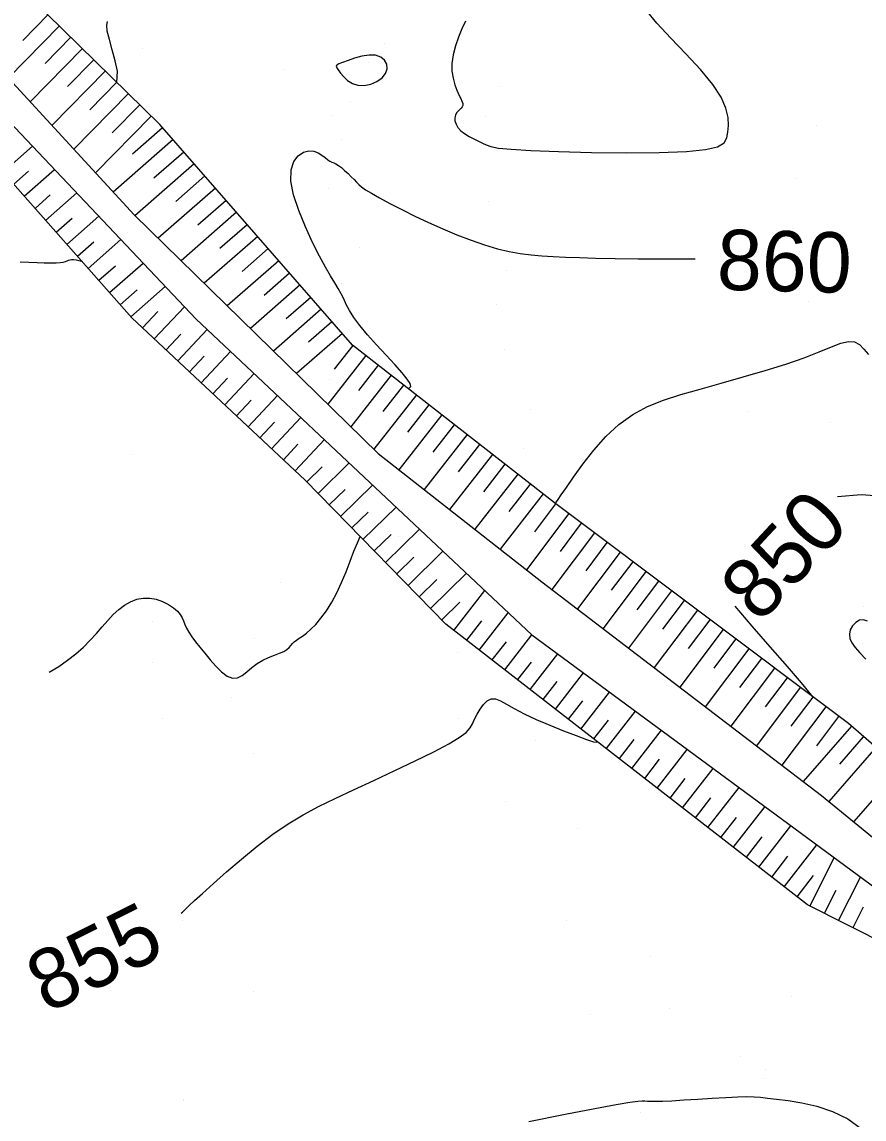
# Model space of a CAD drawing. Extents: x 400243 to 403697, y 4403637 to 4408083.
# Drawn here: x 402920.2 to 403024.9, y 4406214.4 to 4406350.8 of the extents above; entities that cross this region are included whole.
import ezdxf

# ---------------------------------------------------------------- set-up
doc = ezdxf.new("R2010")
doc.units = 0
doc.layers.add('HH_IC', color=7, linetype='Continuous')

msp = doc.modelspace()

# ---------------------------------------------------------------- linework, layer by layer
at = {"layer": 'HH_IC'}
for p, q in [((402937.32, 4406338.07), (402905.56, 4406369.26)), ((402902.34, 4406361.38), (402934.09, 4406326.86)), ((402933.83, 4406314.03), (402899.67, 4406352.63)), ((402920.25, 4406348.54), (402923.4, 4406351.74)), ((402924.82, 4406350.34), (402918.46, 4406343.86)), ((402923.03, 4406345.66), (402926.25, 4406348.94)), ((402927.68, 4406347.54), (402921.17, 4406340.91)), ((402965.24, 4406348.17), (402965.24, 4406348.17)), ((402935.15, 4406347.47), (402935.15, 4406347.47)), ((402925.82, 4406342.79), (402929.11, 4406346.14)), ((402952.66, 4406344.92), (402952.66, 4406344.92)), ((402963.19, 4406345.75), (402963.19, 4406345.75)), ((402930.53, 4406344.74), (402923.88, 4406337.96)), ((402914.74, 4406342.46), (402941.82, 4406313.88)), ((402928.6, 4406339.91), (402931.96, 4406343.34)), ((402979.62, 4406342.84), (402979.62, 4406342.84)), ((402933.39, 4406341.93), (402926.59, 4406335.01)), ((402961.03, 4406340.99), (402961.03, 4406340.99)), ((402931.38, 4406337.04), (402934.81, 4406340.53)), ((402936.24, 4406339.13), (402929.3, 4406332.07)), ((402937.32, 4406338.07), (402937.32, 4406338.07)), ((402961.26, 4406310.65), (402937.32, 4406338.07)), ((402958.61, 4406339.21), (402958.61, 4406339.21)), ((402977.8, 4406339.04), (402977.8, 4406339.04)), ((402933.89, 4406334.43), (402937.64, 4406337.7)), ((403018.9, 4406337.92), (403018.9, 4406337.92)), ((402917.8, 4406332.14), (402921.45, 4406335.38)), ((402938.96, 4406336.2), (402931.49, 4406329.68)), ((402959.91, 4406336.23), (402959.91, 4406336.23)), ((402936.56, 4406331.45), (402940.27, 4406334.69)), ((402941.59, 4406333.19), (402934.21, 4406326.74)), ((402920.98, 4406332.29), (402919.13, 4406330.65)), ((402920.45, 4406329.15), (402924.21, 4406332.47)), ((402939.27, 4406328.51), (402942.9, 4406331.68)), ((403016.5, 4406331.4), (403016.5, 4406331.4)), ((402944.22, 4406330.17), (402937.08, 4406323.94)), ((402958.32, 4406330.17), (402958.32, 4406330.17)), ((402962.37, 4406331.07), (402962.37, 4406331.07)), ((402923.68, 4406329.34), (402921.78, 4406327.65)), ((402923.1, 4406326.15), (402926.96, 4406329.57)), ((402942.02, 4406325.6), (402945.53, 4406328.67)), ((402978.15, 4406328.51), (402978.15, 4406328.51)), ((402946.85, 4406327.16), (402939.95, 4406321.13)), ((402926.38, 4406326.38), (402924.43, 4406324.66)), ((402925.75, 4406323.16), (402929.71, 4406326.66)), ((402934.09, 4406326.86), (402934.09, 4406326.86)), ((402934.09, 4406326.86), (402964.47, 4406297.16)), ((402944.77, 4406322.69), (402948.16, 4406325.65)), ((402929.08, 4406323.43), (402927.08, 4406321.66)), ((402928.4, 4406320.16), (402932.46, 4406323.76)), ((402949.48, 4406324.15), (402942.82, 4406318.33)), ((403017.15, 4406323.62), (403017.15, 4406323.62)), ((402947.52, 4406319.78), (402950.79, 4406322.64)), ((402962.13, 4406322.78), (402962.13, 4406322.78)), ((402931.78, 4406320.48), (402929.73, 4406318.66)), ((402931.05, 4406317.17), (402935.22, 4406320.85)), ((402952.11, 4406321.13), (402945.69, 4406315.52)), ((402950.27, 4406316.87), (402953.42, 4406319.63)), ((402980.38, 4406319.92), (402980.38, 4406319.92)), ((402934.49, 4406317.53), (402932.38, 4406315.67)), ((402933.7, 4406314.17), (402937.97, 4406317.94)), ((402954.74, 4406318.12), (402948.56, 4406312.72)), ((402959.84, 4406318.33), (402959.84, 4406318.33)), ((402953.02, 4406313.96), (402956.06, 4406316.61)), ((402937.07, 4406314.83), (402935.15, 4406312.79)), ((402936.61, 4406311.42), (402940.36, 4406315.42)), ((402957.37, 4406315.11), (402951.42, 4406309.91)), ((402979.17, 4406315.7), (402979.17, 4406315.7)), ((403018, 4406316.08), (403018, 4406316.08)), ((402933.83, 4406314.03), (402933.83, 4406314.03)), ((402955.39, 4406293.83), (402933.83, 4406314.03)), ((402941.82, 4406313.88), (402941.82, 4406313.88)), ((402941.82, 4406313.88), (402983.55, 4406274.63)), ((402955.77, 4406311.06), (402958.69, 4406313.6)), ((402961.03, 4406314.21), (402961.03, 4406314.21)), ((402939.53, 4406308.69), (402943.19, 4406312.59)), ((402960, 4406312.09), (402954.29, 4406307.11)), ((402939.9, 4406312.01), (402938.07, 4406310.06)), ((402942.45, 4406305.95), (402946.1, 4406309.85)), ((402962.9, 4406309.37), (402958.18, 4406303.31)), ((402959.03, 4406307.66), (402961.33, 4406310.6)), ((402961.26, 4406310.65), (402961.26, 4406310.65)), ((402986.39, 4406291.02), (402961.26, 4406310.65)), ((402980.21, 4406310.14), (402980.21, 4406310.14)), ((402942.82, 4406309.27), (402940.99, 4406307.32)), ((402962.05, 4406305.02), (402964.48, 4406308.13)), ((402945.37, 4406303.22), (402949.01, 4406307.11)), ((402966.06, 4406306.9), (402961.05, 4406300.5)), ((402962.08, 4406307.43), (402962.08, 4406307.43)), ((402945.73, 4406306.53), (402943.91, 4406304.59)), ((402958.42, 4406306.38), (402958.42, 4406306.38)), ((402965.06, 4406302.38), (402967.63, 4406305.67)), ((402948.29, 4406300.48), (402951.93, 4406304.37)), ((402969.21, 4406304.44), (402963.93, 4406297.69)), ((402948.65, 4406303.8), (402946.83, 4406301.85)), ((402962.72, 4406303.11), (402962.72, 4406303.11)), ((402968.12, 4406299.8), (402970.78, 4406303.21)), ((402983.37, 4406302.66), (402983.37, 4406302.66)), ((402951.2, 4406297.75), (402954.84, 4406301.63)), ((402972.36, 4406301.98), (402967.03, 4406295.15)), ((403010.33, 4406302.41), (403010.33, 4406302.41)), ((402951.57, 4406301.06), (402949.75, 4406299.12)), ((402971.27, 4406297.33), (402973.94, 4406300.75)), ((403020.71, 4406301.01), (403020.71, 4406301.01)), ((402954.12, 4406295.01), (402957.76, 4406298.89)), ((402975.51, 4406299.52), (402970.18, 4406292.69)), ((402954.48, 4406298.32), (402952.66, 4406296.38)), ((402964.47, 4406297.16), (402964.47, 4406297.16)), ((402964.47, 4406297.16), (402984.82, 4406281.21)), ((402978.66, 4406297.05), (402973.32, 4406290.22)), ((402974.42, 4406294.87), (402977.09, 4406298.28)), ((402982.47, 4406297.84), (402982.47, 4406297.84)), ((402933.94, 4406296.98), (402933.94, 4406296.98)), ((402956.97, 4406292.21), (402960.84, 4406295.99)), ((402977.57, 4406292.4), (402980.24, 4406295.82)), ((402957.48, 4406295.5), (402955.57, 4406293.64)), ((402981.82, 4406294.59), (402976.47, 4406287.75)), ((402955.39, 4406293.83), (402955.39, 4406293.83)), ((402972.88, 4406275.93), (402955.39, 4406293.83)), ((402959.77, 4406289.35), (402963.76, 4406293.24)), ((402980.72, 4406289.94), (402983.39, 4406293.36)), ((402960.33, 4406292.7), (402958.37, 4406290.78)), ((402984.97, 4406292.13), (402979.62, 4406285.28)), ((402962.56, 4406286.49), (402966.67, 4406290.5)), ((402981.17, 4406291.17), (402981.17, 4406291.17)), ((402983.94, 4406287.42), (402986.55, 4406290.9)), ((402986.39, 4406291.02), (402986.39, 4406291.02)), ((403022.92, 4406263.59), (402986.39, 4406291.02)), ((402963.19, 4406289.89), (402961.17, 4406287.92)), ((402988.15, 4406289.7), (402982.9, 4406282.71)), ((402965.36, 4406283.63), (402969.59, 4406287.76)), ((402987.11, 4406284.99), (402989.74, 4406288.5)), ((402966.05, 4406287.09), (402963.96, 4406285.06)), ((402966.92, 4406286.83), (402966.92, 4406286.83)), ((402991.34, 4406287.3), (402986.06, 4406280.26)), ((402968.16, 4406280.76), (402972.51, 4406285.02)), ((402994.54, 4406284.89), (402989.24, 4406277.83)), ((402990.3, 4406282.57), (402992.94, 4406286.1)), ((402968.9, 4406284.29), (402966.76, 4406282.19)), ((402993.48, 4406280.15), (402996.14, 4406283.69)), ((402970.95, 4406277.9), (402975.42, 4406282.27)), ((402997.74, 4406282.49), (402992.42, 4406275.4)), ((402952.36, 4406281.14), (402952.36, 4406281.14)), ((402971.76, 4406281.49), (402969.55, 4406279.33)), ((402984.82, 4406281.21), (402984.82, 4406281.21)), ((402984.82, 4406281.21), (403019.57, 4406254.65)), ((402996.67, 4406277.74), (402999.34, 4406281.29)), ((402973.86, 4406275.17), (402977.71, 4406280.12)), ((403000.94, 4406280.09), (402995.59, 4406272.97)), ((402974.62, 4406278.69), (402972.35, 4406276.47)), ((402999.86, 4406275.32), (403002.54, 4406278.89)), ((403024.81, 4406278.11), (403024.81, 4406278.11)), ((402977.02, 4406272.72), (402980.63, 4406277.37)), ((403004.14, 4406277.69), (402998.77, 4406270.54)), ((402936.44, 4406276.3), (402936.44, 4406276.3)), ((402972.88, 4406275.93), (402972.88, 4406275.93)), ((403017.84, 4406241.02), (402972.88, 4406275.93)), ((402977.31, 4406276.34), (402975.44, 4406273.94)), ((403007.34, 4406275.29), (403001.95, 4406268.11)), ((403003.05, 4406272.91), (403005.74, 4406276.49)), ((402949.13, 4406274.15), (402949.13, 4406274.15)), ((402980.18, 4406270.26), (402983.56, 4406274.62)), ((402983.55, 4406274.63), (402983.55, 4406274.63)), ((402983.55, 4406274.63), (403038.5, 4406234.11)), ((403006.24, 4406270.49), (403008.94, 4406274.09)), ((402980.35, 4406273.74), (402978.6, 4406271.49)), ((403010.54, 4406272.89), (403005.13, 4406265.68)), ((403024.65, 4406273.51), (403024.65, 4406273.51)), ((402936.39, 4406271.12), (402936.39, 4406271.12)), ((402974.36, 4406272.44), (402974.36, 4406272.44)), ((402983.47, 4406271.23), (402981.76, 4406269.04)), ((402983.34, 4406267.81), (402986.78, 4406272.24)), ((403009.43, 4406268.08), (403012.14, 4406271.68)), ((402986.5, 4406265.36), (402990, 4406269.87)), ((403013.73, 4406270.48), (403008.31, 4406263.26)), ((402986.66, 4406268.82), (402984.92, 4406266.58)), ((403012.62, 4406265.66), (403015.33, 4406269.28)), ((402989.66, 4406262.9), (402993.22, 4406267.5)), ((403016.93, 4406268.08), (403011.49, 4406260.83)), ((402946.18, 4406266.88), (402946.18, 4406266.88)), ((402989.85, 4406266.41), (402988.08, 4406264.13)), ((403020.13, 4406265.68), (403014.66, 4406258.4)), ((403015.8, 4406263.25), (403018.53, 4406266.88)), ((402992.82, 4406260.45), (402996.44, 4406265.12)), ((403018.99, 4406260.83), (403021.73, 4406264.48)), ((402937.58, 4406264.27), (402937.58, 4406264.27)), ((402974.47, 4406264.22), (402974.47, 4406264.22)), ((402993.04, 4406263.99), (402991.24, 4406261.68)), ((403023.31, 4406263.25), (403017.31, 4406256.38)), ((403022.92, 4406263.59), (403022.92, 4406263.59)), ((403043.88, 4406245.29), (403022.92, 4406263.59)), ((402996.23, 4406261.58), (402994.4, 4406259.22)), ((402995.98, 4406258), (402999.66, 4406262.75)), ((403021.86, 4406258.55), (403024.81, 4406261.93)), ((402983.96, 4406261.46), (402983.96, 4406261.46)), ((402999.14, 4406255.54), (403002.88, 4406260.37)), ((403026.32, 4406260.62), (403020.47, 4406253.91)), ((402948.94, 4406259.9), (402948.94, 4406259.9)), ((402999.41, 4406259.16), (402997.56, 4406256.77)), ((403002.3, 4406253.09), (403006.1, 4406258)), ((403029.33, 4406257.99), (403023.56, 4406251.38)), ((403002.6, 4406256.75), (403000.72, 4406254.32)), ((403005.45, 4406250.64), (403009.32, 4406255.62)), ((402980.27, 4406253.9), (402980.27, 4406253.9)), ((403005.79, 4406254.34), (403003.87, 4406251.86)), ((403019.57, 4406254.65), (403019.57, 4406254.65)), ((403019.57, 4406254.65), (403041.16, 4406236.95)), ((403008.61, 4406248.18), (403012.55, 4406253.25)), ((403008.98, 4406251.92), (403007.03, 4406249.41)), ((403011.77, 4406245.73), (403015.77, 4406250.87)), ((402952.14, 4406249.58), (402952.14, 4406249.58)), ((402989.28, 4406250.51), (402989.28, 4406250.51)), ((403012.17, 4406249.51), (403010.19, 4406246.96)), ((403014.93, 4406243.28), (403018.99, 4406248.5)), ((403015.36, 4406247.1), (403013.35, 4406244.5)), ((403018.13, 4406240.88), (403021.16, 4406246.9)), ((403018.55, 4406244.68), (403016.51, 4406242.05)), ((403021.7, 4406239.08), (403024.42, 4406244.49)), ((403021.35, 4406242.84), (403019.91, 4406239.98)), ((403017.83, 4406241), (403017.83, 4406241)), ((403017.84, 4406241.02), (403017.84, 4406241.02)), ((403057.81, 4406220.9), (403017.84, 4406241.02)), ((403024.77, 4406240.73), (403023.48, 4406238.18)), ((402940.17, 4406239.09), (402940.17, 4406239.09)), ((402987.85, 4406239.07), (402987.85, 4406239.07)), ((402998.32, 4406234.58), (402998.32, 4406234.58)), ((402948.99, 4406230.23), (402948.99, 4406230.23)), ((403015.8, 4406229.65), (403015.8, 4406229.65)), ((402990.89, 4406227.45), (402990.89, 4406227.45)), ((403000.71, 4406228.12), (403000.71, 4406228.12)), ((403009.48, 4406222.15), (403009.48, 4406222.15)), ((403012.5, 4406219.41), (403012.5, 4406219.41)), ((403012.6, 4406220.61), (403012.6, 4406220.61)), ((402940.28, 4406216.78), (402940.28, 4406216.78)), ((402940.29, 4406216.76), (402940.29, 4406216.76)), ((402997.08, 4406215.24), (402997.08, 4406215.24))]:
    msp.add_line(p, q, dxfattribs=at)
for points in [[(402975.3, 4406350.93), (402974.86, 4406349.98), (402974.44, 4406348.93), (402974.06, 4406347.84), (402973.77, 4406346.74), (402973.62, 4406345.68), (402973.63, 4406344.71), (402973.77, 4406343.82), (402973.99, 4406343.03), (402974.25, 4406342.35), (402974.5, 4406341.78), (402974.71, 4406341.32), (402974.87, 4406340.96), (402974.96, 4406340.68), (402974.97, 4406340.46), (402974.91, 4406340.27), (402974.78, 4406340.1), (402974.59, 4406339.93), (402974.38, 4406339.74), (402974.19, 4406339.51), (402974.05, 4406339.24), (402973.98, 4406338.91), (402974, 4406338.53), (402974.13, 4406338.12), (402974.36, 4406337.71), (402974.72, 4406337.31), (402975.2, 4406336.94), (402975.76, 4406336.6), (402976.35, 4406336.29), (402976.92, 4406336.01), (402977.44, 4406335.76), (402977.88, 4406335.54), (402978.46, 4406335.33), (402979.41, 4406335.15), (402980.99, 4406334.99), (402983.43, 4406334.83), (402986.86, 4406334.7), (402990.97, 4406334.6), (402995.28, 4406334.55), (402999.37, 4406334.58), (403002.77, 4406334.7), (403005.16, 4406334.95), (403006.65, 4406335.31), (403007.46, 4406335.79), (403007.81, 4406336.4), (403007.93, 4406337.11), (403008, 4406337.96), (403007.95, 4406338.94), (403007.68, 4406340.1), (403007.09, 4406341.47), (403006.06, 4406343.07), (403004.54, 4406344.9), (403002.72, 4406346.86), (403000.84, 4406348.83), (402999.12, 4406350.68), (402997.81, 4406352.27)], [(402931.97, 4406343.32), (402932.02, 4406344.73), (402931.75, 4406345.99), (402931.39, 4406347.35), (402931.03, 4406348.64), (402930.77, 4406349.7), (402930.69, 4406350.42), (402930.78, 4406350.88)], [(402961.93, 4406342.95), (402962.71, 4406342.94), (402963.52, 4406343.11), (402964.29, 4406343.44), (402964.93, 4406343.89), (402965.38, 4406344.42), (402965.58, 4406345), (402965.53, 4406345.57), (402965.25, 4406346.07), (402964.78, 4406346.47), (402964.12, 4406346.69), (402963.31, 4406346.71), (402962.41, 4406346.56), (402961.52, 4406346.32), (402960.7, 4406346.04), (402960.03, 4406345.79), (402959.57, 4406345.61), (402959.31, 4406345.47), (402959.22, 4406345.33), (402959.29, 4406345.14), (402959.48, 4406344.86), (402959.77, 4406344.46), (402960.16, 4406344), (402960.65, 4406343.54), (402961.24, 4406343.17), (402961.93, 4406342.95)], [(402968.22, 4406305.21), (402968.51, 4406305.48), (402968.41, 4406305.86), (402968.06, 4406306.42), (402967.43, 4406307.21), (402966.52, 4406308.22), (402965.43, 4406309.4), (402964.26, 4406310.66), (402963.13, 4406311.91), (402962.16, 4406313.08), (402961.42, 4406314.09), (402960.88, 4406314.95), (402960.49, 4406315.71), (402960.16, 4406316.4), (402959.85, 4406317.04), (402959.49, 4406317.68), (402959.06, 4406318.39), (402958.54, 4406319.25), (402957.92, 4406320.33), (402957.17, 4406321.71), (402956.3, 4406323.42), (402955.4, 4406325.36), (402954.58, 4406327.37), (402953.94, 4406329.32), (402953.6, 4406331.04), (402953.63, 4406332.42), (402953.96, 4406333.46), (402954.51, 4406334.18), (402955.16, 4406334.63), (402955.84, 4406334.81), (402956.45, 4406334.77), (402956.98, 4406334.57), (402957.45, 4406334.28), (402957.84, 4406333.96), (402958.17, 4406333.68), (402958.45, 4406333.5), (402958.69, 4406333.39), (402958.93, 4406333.3), (402959.19, 4406333.18), (402959.5, 4406333), (402959.87, 4406332.73), (402960.28, 4406332.37), (402960.7, 4406331.98), (402961.11, 4406331.59), (402961.46, 4406331.22), (402961.75, 4406330.91), (402962.03, 4406330.63), (402962.38, 4406330.33), (402962.88, 4406329.97), (402963.62, 4406329.52), (402964.63, 4406328.94), (402965.91, 4406328.25), (402967.38, 4406327.49), (402969, 4406326.69), (402970.72, 4406325.89), (402972.48, 4406325.1), (402974.25, 4406324.36), (402976, 4406323.69), (402977.68, 4406323.1), (402979.27, 4406322.62), (402980.74, 4406322.27), (402982.12, 4406322.02), (402983.46, 4406321.85), (402984.82, 4406321.74), (402986.23, 4406321.66), (402987.75, 4406321.59), (402989.48, 4406321.52), (402991.49, 4406321.47), (402993.9, 4406321.42), (402996.79, 4406321.39), (403000.19, 4406321.37), (403003.88, 4406321.37)], [(402919.94, 4406321.01), (402921.03, 4406320.94), (402922.03, 4406320.9), (402922.93, 4406320.87), (402923.72, 4406320.86), (402924.39, 4406320.87), (402924.91, 4406320.9), (402925.29, 4406320.96), (402925.56, 4406321.04), (402925.76, 4406321.11), (402925.93, 4406321.19), (402926.1, 4406321.24), (402926.32, 4406321.27), (402926.58, 4406321.27), (402926.88, 4406321.24), (402927.21, 4406321.17), (402927.57, 4406321.08), (402927.6, 4406321.07)], [(402986.5, 4406291), (402986.53, 4406291.03), (402986.62, 4406291.15), (402986.83, 4406291.45), (402987.22, 4406292.01), (402987.85, 4406292.92), (402988.75, 4406294.24), (402989.9, 4406295.83), (402991.25, 4406297.56), (402992.76, 4406299.27), (402994.39, 4406300.79), (402996.11, 4406302.02), (402997.94, 4406302.99), (402999.92, 4406303.79), (403002.09, 4406304.49), (403004.48, 4406305.18), (403007.1, 4406305.91), (403009.85, 4406306.69), (403012.57, 4406307.49), (403015.14, 4406308.28), (403017.42, 4406309.06), (403019.3, 4406309.79), (403020.8, 4406310.41), (403022, 4406310.88), (403022.93, 4406311.11), (403023.68, 4406311.06), (403024.29, 4406310.7), (403024.85, 4406310.12), (403025.41, 4406309.47)], [(403021.56, 4406291.81), (403024.52, 4406292.05), (403027.32, 4406291.85)], [(402923.54, 4406269.96), (402924.73, 4406270.67), (402925.83, 4406271.45), (402926.85, 4406272.26), (402927.79, 4406273.1), (402928.65, 4406273.95), (402929.43, 4406274.8), (402930.14, 4406275.63), (402930.83, 4406276.41), (402931.5, 4406277.13), (402932.19, 4406277.77), (402932.9, 4406278.3), (402933.65, 4406278.73), (402934.43, 4406279.03), (402935.23, 4406279.19), (402936.04, 4406279.19), (402936.86, 4406279.04), (402937.65, 4406278.76), (402938.37, 4406278.4), (402939, 4406277.98), (402939.5, 4406277.56), (402939.84, 4406277.14), (402940.07, 4406276.74), (402940.24, 4406276.34), (402940.4, 4406275.92), (402940.6, 4406275.45), (402940.9, 4406274.94), (402941.28, 4406274.38), (402941.75, 4406273.76), (402942.29, 4406273.07), (402942.89, 4406272.32), (402943.56, 4406271.51), (402944.25, 4406270.72), (402944.96, 4406270.02), (402945.66, 4406269.49), (402946.33, 4406269.22), (402946.95, 4406269.27), (402947.54, 4406269.56), (402948.13, 4406270.02), (402948.73, 4406270.54), (402949.39, 4406271.05), (402950.1, 4406271.47), (402950.83, 4406271.8), (402951.54, 4406272.08), (402952.19, 4406272.32), (402952.72, 4406272.55), (402953.11, 4406272.79), (402953.39, 4406273.04), (402953.6, 4406273.28), (402953.79, 4406273.52), (402954.01, 4406273.75), (402954.29, 4406273.96), (402954.64, 4406274.19), (402955.06, 4406274.46), (402955.55, 4406274.82), (402956.09, 4406275.3), (402956.7, 4406275.92), (402957.34, 4406276.69), (402958.01, 4406277.61), (402958.67, 4406278.66), (402959.3, 4406279.84), (402959.9, 4406281.12), (402960.45, 4406282.46), (402960.96, 4406283.78), (402961.43, 4406285), (402961.87, 4406286.05), (402962.23, 4406286.83)], [(403018.54, 4406266.87), (403017.1, 4406268.66), (403015.33, 4406270.69), (403013.2, 4406273.12), (403010.95, 4406275.69), (403008.85, 4406278.16)], [(403025.31, 4406276.33), (403024.79, 4406276.5), (403024.29, 4406276.43), (403023.83, 4406276.15), (403023.44, 4406275.74), (403023.16, 4406275.24), (403023.04, 4406274.7), (403023.1, 4406274.18), (403023.34, 4406273.64), (403023.75, 4406273.05), (403024.34, 4406272.38), (403025.1, 4406271.59)], [(402939.95, 4406239.99), (402940.1, 4406240.14), (402940.27, 4406240.31), (402940.53, 4406240.56), (402940.96, 4406240.95), (402941.62, 4406241.56), (402942.61, 4406242.45), (402943.96, 4406243.68), (402945.61, 4406245.14), (402947.46, 4406246.73), (402949.42, 4406248.33), (402951.37, 4406249.81), (402953.26, 4406251.1), (402955.13, 4406252.23), (402957.05, 4406253.27), (402959.11, 4406254.28), (402961.38, 4406255.35), (402963.89, 4406256.51), (402966.51, 4406257.73), (402969.06, 4406258.93), (402971.36, 4406260.06), (402973.23, 4406261.04), (402974.54, 4406261.84), (402975.38, 4406262.48), (402975.88, 4406263.03), (402976.19, 4406263.56), (402976.44, 4406264.11), (402976.75, 4406264.73), (402977.12, 4406265.36), (402977.55, 4406265.94), (402978.02, 4406266.39), (402978.52, 4406266.64), (402979.05, 4406266.65), (402979.66, 4406266.42), (402980.41, 4406266.01), (402981.37, 4406265.45), (402982.6, 4406264.8), (402984.11, 4406264.09), (402985.8, 4406263.38), (402987.51, 4406262.69), (402989.08, 4406262.09), (402990.37, 4406261.61), (402991.23, 4406261.31), (402991.65, 4406261.25), (402991.63, 4406261.37)], [(402983.19, 4406214.09), (402987.69, 4406215), (402991.4, 4406215.71), (402994.03, 4406216.2), (402995.73, 4406216.49), (402996.73, 4406216.63), (402997.27, 4406216.67), (402997.61, 4406216.66), (402997.94, 4406216.64), (402998.37, 4406216.62), (402998.97, 4406216.62), (402999.81, 4406216.63), (403000.97, 4406216.68), (403002.47, 4406216.77), (403004.19, 4406216.87), (403005.99, 4406216.99), (403007.7, 4406217.09), (403009.17, 4406217.16), (403010.3, 4406217.19), (403011.19, 4406217.17), (403011.99, 4406217.11), (403012.87, 4406217.01), (403013.97, 4406216.88), (403015.41, 4406216.7), (403017.13, 4406216.42), (403019.01, 4406215.99), (403020.95, 4406215.34), (403022.83, 4406214.41), (403024.56, 4406213.18)]]:
    msp.add_lwpolyline(points, dxfattribs=at)

# ---------------------------------------------------------------- texts
for s, rotation, p in [('860', 358.5158, (403006.51, 4406317.55)), ('850', 47.0496, (403011.89, 4406275.91)), ('855', 26.6347, (402923.3, 4406227.45))]:
    msp.add_text(s, height=7.5, rotation=rotation, dxfattribs=at).set_placement(p)

doc.saveas('drawing.dxf')
